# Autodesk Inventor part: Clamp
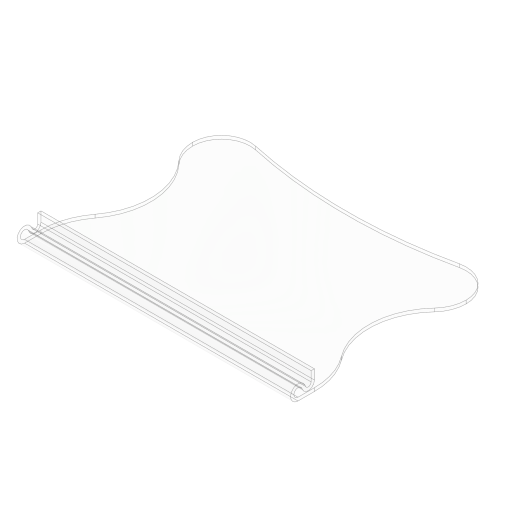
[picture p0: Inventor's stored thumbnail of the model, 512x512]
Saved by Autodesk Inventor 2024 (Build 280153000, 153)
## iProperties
Created: 2024-06
Part Number: Clamp
Material: PET Plastic
Document SubType Name: Modeling
Designer: simon
Density: 1.541 g/cm^3
Appearance: Polycarbonate - Clear
Author: simon
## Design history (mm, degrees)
sketch "Sketch1"
  geometry: L1 (0, 0)-(0, 180); L2 (6.094, 165)-(15, 165); A1 r 3.834 centre (3.834, 180) between (5.448, 176.523) and (0, 180); A2 r 12.937 centre (0, 188.257) between (4.236, 176.033) and (5.448, 176.523); A3 r 5.673 centre (6.094, 170.673) between (4.236, 176.033) and (6.094, 165); 1 further point
  constraints: 7 point on circle, 4 end point, 4 tangent, 3 centre point, 1 horizontal, 1 point on line, 1 vertical
  dimensions: "d0" = 180 distance of L1.start L1.end; "d1" = 15 distance from line of L1 L2.end; "d2" = 0.5 distance from line of L1 point (0.5, 169.731); "d9" = 165 distance from line of L1.start L2
extrude_surface "ExtrusionSrf1" sketch "Sketch1" dims "d3" = 250, "d4" = 0
thicken "Thicken1" dims "d5" = 3, "d6" = 1
sketch "Sketch2"
  geometry: L1 (0, 180)-(250, 180) reference; L2 (125, 180)-(125, 15); L3 (0, 15)-(250, 15) reference; L4 (0, 180)-(0, 0) reference; L5 (125, 169.348)-(181.165, 169.348); L6 (0, 180)-(250, 180) reference; L7 (0, 180)-(0, 0) reference; L8 (0, 153.742)-(0, 180); L9 (0, 180)-(250, 180); L10 (250, 0)-(250, 180) reference; L11 (250, 153.742)-(250, 180); L12 (0, 15)-(250, 15) reference; A1 r 30.471 centre (30.471, 153.742) between (0, 153.742) and (0, 153.742); A2 r 26.258 centre (26.258, 153.742) between (31.858, 179.396) and (0, 153.742); A3 r 436.716 centre (125, 606.063) between (31.858, 179.396) and (125, 169.348); A4 r 30.471 centre (219.529, 153.742) between (250, 153.742) and (250, 153.742); A5 r 26.258 centre (223.742, 153.742) between (250, 153.742) and (218.142, 179.396); A6 r 436.716 centre (125, 606.063) between (125, 169.348) and (218.142, 179.396); A7 r 30.471 centre (30.471, 153.742) between (0, 153.742) and (8.173, 132.976); A8 r 63.057 centre (-37.971, 90) between (12.396, 52.062) and (8.173, 132.976); A9 r 61.602 centre (61.602, 15) between (12.396, 52.062) and (0, 15); A10 r 30.471 centre (219.529, 153.742) between (241.827, 132.976) and (250, 153.742); A11 r 63.057 centre (287.971, 90) between (241.827, 132.976) and (237.604, 52.062); A12 r 61.602 centre (188.398, 15) between (250, 15) and (237.604, 52.062); 13 further points
  constraints: 26 point on circle, 12 centre point, 11 symmetric about line, 10 end point, 9 tangent, 3 collinear, 3 midpoint, 3 point on line, 1 coincident, 1 perpendicular, 6 other
  dimensions: "d10" = 200 distance of point (225, 93.287) point (25, 93.287); "d11" = 75 vertical distance of point (125, 15) A8.centre
extrude "Extrusion1" cut sketch "Sketch2" extent not by distance; stored distance "d7" = 0; taper "d8" = 0 deg
body "Solid1"
body "Srf1"
